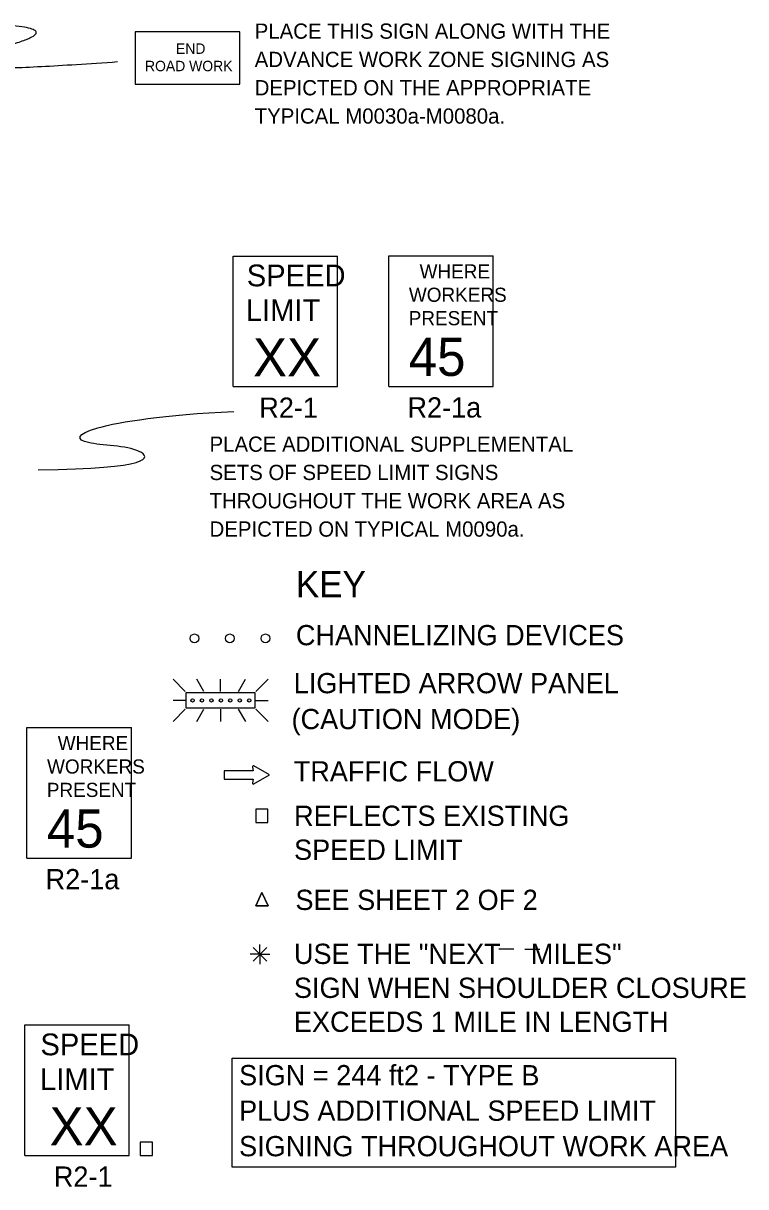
# Model space of a CAD drawing. Extents: x 16730 to 18471, y 7027 to 8225.
# Drawn here: x 17113 to 17445, y 7672 to 8207 of the extents above; entities that cross this region are included whole.
import ezdxf

# ---------------------------------------------------------------- set-up
doc = ezdxf.new("R2010")
doc.units = 0
for name, color, linetype in [('MT_SCRATCH_LEVEL_E', 7, 'Continuous'), ('TRAFFIC_SIGNS_PR', 7, 'Continuous'), ('TYPICAL_TEXT_DIMEN_EX', 7, 'Continuous'), ('TYPICAL_TEXT_DIMEN_PR', 7, 'Continuous')]:
    doc.layers.add(name, color=color, linetype=linetype)

msp = doc.modelspace()

# ---------------------------------------------------------------- linework, layer by layer
at = {"layer": 'MT_SCRATCH_LEVEL_E'}
for p, q in [((17218.87, 7863.13), (17205.61, 7863.13)), ((17205.61, 7863.13), (17205.61, 7859.39)), ((17218.87, 7863.13), (17205.61, 7863.13)), ((17205.61, 7863.13), (17205.61, 7859.39)), ((17218.55, 7864.91), (17218.87, 7863.13)), ((17218.55, 7864.91), (17218.87, 7863.13)), ((17226.48, 7861.28), (17219.24, 7865.39)), ((17226.48, 7861.28), (17219.24, 7865.39)), ((17205.61, 7859.39), (17218.87, 7859.39)), ((17205.61, 7859.39), (17218.87, 7859.39)), ((17218.87, 7859.39), (17218.55, 7857.62)), ((17218.87, 7859.39), (17218.55, 7857.62)), ((17219.24, 7857.14), (17226.48, 7861.28)), ((17219.24, 7857.14), (17226.48, 7861.28))]:
    msp.add_line(p, q, dxfattribs=at)
for centre, start, end in [((17219.01, 7864.99), 60.4248, 189.9638), ((17219.01, 7864.99), 60.4248, 189.9638), ((17219.01, 7857.55), 170.0362, 299.7731), ((17219.01, 7857.55), 170.0362, 299.7731)]:
    msp.add_arc(centre, 0.463, start, end, dxfattribs=at)
at = {"layer": 'TRAFFIC_SIGNS_PR'}
for p, q in [((17209.69, 8099.63), (17257.69, 8099.63)), ((17209.69, 8039.63), (17209.69, 8099.63)), ((17257.69, 8039.63), (17257.69, 8099.63)), ((17281.19, 8099.74), (17329.19, 8099.74)), ((17281.19, 8039.74), (17281.19, 8099.74)), ((17329.19, 8039.74), (17329.19, 8099.74)), ((17209.69, 8039.63), (17257.69, 8039.63)), ((17281.19, 8039.74), (17329.19, 8039.74)), ((17182.12, 7905.19), (17187.76, 7899.55)), ((17196.3, 7899.55), (17193.04, 7905.19)), ((17203.93, 7899.55), (17203.93, 7905.19)), ((17212.2, 7899.55), (17215.46, 7905.19)), ((17220.1, 7899.55), (17225.74, 7905.2)), ((17187.76, 7895.49), (17182.12, 7895.49)), ((17191.03, 7895.49), (17191.03, 7895.49)), ((17195.38, 7895.49), (17195.38, 7895.49)), ((17199.73, 7895.49), (17199.73, 7895.49)), ((17204.08, 7895.49), (17204.08, 7895.49)), ((17208.42, 7895.49), (17208.42, 7895.49)), ((17212.77, 7895.49), (17212.77, 7895.49)), ((17217.12, 7895.49), (17217.12, 7895.49)), ((17220.1, 7895.49), (17225.74, 7895.49)), ((17182.12, 7885.79), (17187.76, 7891.43)), ((17192.99, 7885.79), (17196.25, 7891.43)), ((17203.93, 7891.43), (17203.93, 7885.79)), ((17215.51, 7885.79), (17212.25, 7891.43)), ((17220.1, 7891.43), (17225.74, 7885.78)), ((17115.04, 7883.05), (17163.04, 7883.05)), ((17115.04, 7823.05), (17115.04, 7883.05)), ((17163.04, 7823.05), (17163.04, 7883.05)), ((17115.04, 7823.05), (17163.04, 7823.05)), ((17114.03, 7746.41), (17162.03, 7746.41)), ((17114.03, 7686.41), (17114.03, 7746.41)), ((17162.03, 7686.41), (17162.03, 7746.41)), ((17114.03, 7686.41), (17162.03, 7686.41))]:
    msp.add_line(p, q, dxfattribs=at)
for points in [[(17164.73, 8178.59), (17212.73, 8178.59), (17212.73, 8202.59), (17164.73, 8202.59)], [(17219.64, 7891.89), (17188.22, 7891.89), (17188.22, 7899.09), (17219.64, 7899.09)], [(17220.1, 7839.45), (17225.69, 7839.45), (17225.69, 7845.62), (17220.1, 7845.62)], [(17167.05, 7686.41), (17172.64, 7686.41), (17172.64, 7692.58), (17167.05, 7692.58)]]:
    msp.add_lwpolyline(points, close=True, dxfattribs=at)
for points in [[(17222.97, 7807.25), (17220.18, 7801.08)], [(17220.18, 7801.08), (17222.97, 7807.25)], [(17225.77, 7801.08), (17222.97, 7807.25)], [(17222.97, 7807.25), (17225.77, 7801.08)], [(17220.18, 7801.08), (17225.77, 7801.08)], [(17225.77, 7801.08), (17220.18, 7801.08)]]:
    msp.add_lwpolyline(points, dxfattribs=at)
for centre, radius in [((17191.92, 7924.01), 2), ((17208.22, 7924.01), 2), ((17224.52, 7924.01), 2), ((17191.07, 7895.49), 0.758), ((17195.38, 7895.49), 0.758), ((17199.73, 7895.49), 0.758), ((17204.08, 7895.49), 0.758), ((17208.42, 7895.49), 0.758), ((17212.77, 7895.49), 0.758), ((17217.12, 7895.49), 0.758)]:
    msp.add_circle(centre, radius, dxfattribs=at)
msp.add_open_spline([(17156.66, 8188.77), (17041.44, 8180.53), (17155.34, 8208.11), (17057.4, 8205.95)], degree=2, dxfattribs=at)
at = {"layer": 'TYPICAL_TEXT_DIMEN_EX'}
for p, q in [((17331.67, 7781.4), (17338.67, 7781.4)), ((17343.62, 7781.24), (17350.62, 7781.24))]:
    msp.add_line(p, q, dxfattribs=at)
msp.add_lwpolyline([(17209.32, 7731.13), (17412.91, 7731.13), (17412.91, 7681.05), (17209.32, 7681.05)], close=True, dxfattribs=at)
at = {"layer": 'TYPICAL_TEXT_DIMEN_PR'}
for p, q in [((17218.84, 7782.08), (17225.22, 7775.7)), ((17225.22, 7782.08), (17218.84, 7775.7)), ((17222.03, 7778.89), (17222.03, 7783.34)), ((17222.03, 7778.89), (17217.5, 7778.89)), ((17222.03, 7778.89), (17225.22, 7778.89)), ((17222.03, 7778.89), (17226.51, 7778.89)), ((17222.03, 7778.89), (17222.03, 7774.39))]:
    msp.add_line(p, q, dxfattribs=at)
msp.add_open_spline([(17120.18, 8001.48), (17172.4, 8001.84), (17172.4, 8012.59), (17137.49, 8012.59), (17137.49, 8020.44), (17177.93, 8026.69), (17210.03, 8028.27)], degree=3, dxfattribs=at)

# ---------------------------------------------------------------- texts
at = {"layer": 'TRAFFIC_SIGNS_PR'}
for s, height, p in [('PLACE THIS SIGN ALONG WITH THE', 7, (17219.61, 8199.44)), ('END', 4.789, (17183.48, 8192.5)), ('ADVANCE WORK ZONE SIGNING AS', 7, (17219.61, 8186.44)), ('ROAD WORK', 4.789, (17169.24, 8184.52)), ('DEPICTED ON THE APPROPRIATE', 7, (17219.61, 8173.44)), ('TYPICAL M0030a-M0080a.', 7, (17219.61, 8160.44)), ('SPEED', 10, (17215.98, 8085.71)), ('WHERE', 6.5, (17295.33, 8089.34)), ('WORKERS', 6.5, (17290.42, 8078.59)), ('LIMIT', 10, (17215.57, 8069.71)), ('PRESENT', 6.5, (17290.33, 8067.84)), ('XX', 17.538, (17218.83, 8044.33)), ('45', 17.538, (17290.32, 8044.56)), ('R2-1', 9.3, (17221.71, 8025.33)), ('R2-1a', 9.3, (17289.76, 8025.44)), ('PLACE ADDITIONAL SUPPLEMENTAL', 7, (17198.89, 8009.72)), ('SETS OF SPEED LIMIT SIGNS', 7, (17198.89, 7996.72)), ('THROUGHOUT THE WORK AREA AS', 7, (17198.89, 7983.72)), ('DEPICTED ON TYPICAL M0090a.', 7, (17198.89, 7970.72)), ('WHERE', 6.5, (17129.18, 7872.65)), ('WORKERS', 6.5, (17124.27, 7861.9)), ('PRESENT', 6.5, (17124.18, 7851.15)), ('45', 17.538, (17124.17, 7827.87)), ('R2-1a', 9.3, (17123.61, 7808.75)), ('SPEED', 10, (17121.24, 7732.49)), ('LIMIT', 10, (17121.04, 7716.49)), ('XX', 17.538, (17125.42, 7691.11)), ('R2-1', 9.3, (17127.38, 7672.11))]:
    msp.add_text(s, height=height, dxfattribs=at).set_placement(p)
at = {"layer": 'TYPICAL_TEXT_DIMEN_EX'}
for s, height, p in [('KEY', 12, (17238.54, 7942.89)), ('CHANNELIZING DEVICES', 9.3, (17238.54, 7920.84)), ('LIGHTED ARROW PANEL', 9.3, (17237.55, 7898.79)), ('(CAUTION MODE)', 9.3, (17236.55, 7882.3)), ('TRAFFIC FLOW', 9.3, (17237.55, 7858.29)), ('REFLECTS EXISTING', 9.3, (17237.69, 7837.86)), ('SPEED LIMIT', 9.3, (17237.69, 7822.26)), ('SEE SHEET 2 OF 2', 9.3, (17238.33, 7799.24)), ('USE THE "NEXT    MILES"', 9.3, (17237.63, 7774.44)), ('SIGN WHEN SHOULDER CLOSURE', 9.3, (17237.63, 7758.84)), ('EXCEEDS 1 MILE IN LENGTH', 9.3, (17237.63, 7743.24)), ('SIGN = 244 ft2 - TYPE B', 9.3, (17212.45, 7718.71)), ('PLUS ADDITIONAL SPEED LIMIT', 9.3, (17212.45, 7702.41)), ('SIGNING THROUGHOUT WORK AREA', 9.3, (17212.45, 7686.11))]:
    msp.add_text(s, height=height, dxfattribs=at).set_placement(p)

doc.saveas('drawing.dxf')
